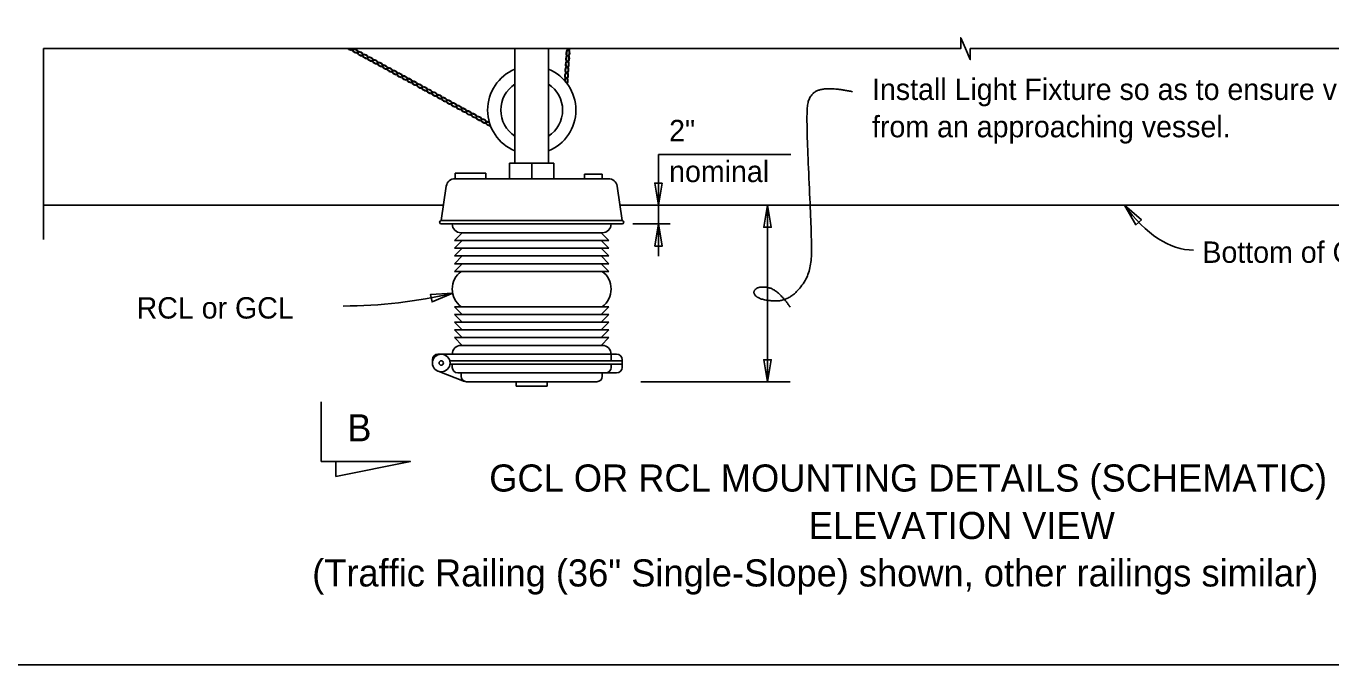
# Model space of a CAD drawing. Extents: x 0 to 20.5, y 0 to 13.
# Drawn here: x 5.78 to 11.94, y 0 to 3.02 of the extents above; entities that cross this region are included whole.
import ezdxf

# ---------------------------------------------------------------- set-up
doc = ezdxf.new("R2010")
doc.units = 0
for name, color, linetype in [('ActivePts-ConstElements', 7, 'Continuous'), ('Dimension', 7, 'Continuous'), ('Miscellaneous', 7, 'Continuous'), ('Miscellaneous1', 7, 'Continuous'), ('NavLight', 7, 'Continuous'), ('SupstrConc', 7, 'Continuous'), ('TextStructures', 7, 'Continuous')]:
    doc.layers.add(name, color=color, linetype=linetype)

msp = doc.modelspace()

# ---------------------------------------------------------------- linework, layer by layer
at = {"layer": 'ActivePts-ConstElements'}
msp.add_lwpolyline([(0, 0), (20.5253, 0), (20.5253, 12.9731), (0, 12.9731)], close=True, dxfattribs=at)
at = {"layer": 'Dimension'}
for p, q in [((8.7613, 2.4096), (8.7613, 2.1697)), ((8.7613, 2.4096), (9.387, 2.4096)), ((8.6296, 2.1697), (8.8874, 2.1697)), ((8.7613, 2.1697), (8.7613, 1.9298)), ((9.2761, 1.3364), (9.2761, 2.1697)), ((8.6404, 2.0813), (8.8171, 2.0813)), ((8.7613, 1.9805), (8.7613, 2.0813)), ((8.6782, 1.3364), (9.3831, 1.3364)), ((7.1685, 1.2409), (7.1685, 0.9597)), ((7.1685, 0.9597), (7.5903, 0.9597)), ((7.5903, 0.9597), (7.2388, 0.8893)), ((7.2388, 0.8893), (7.2388, 0.9597))]:
    msp.add_line(p, q, dxfattribs=at)
for points in [[(5.858, 2.9088), (10.1884, 2.9088), (10.1884, 2.9604), (10.2109, 2.9088), (10.2334, 2.8571), (10.2334, 2.9088), (13.9245, 2.9088)], [(5.858, 2.0075), (5.858, 2.9088)]]:
    msp.add_lwpolyline(points, dxfattribs=at)
for points in [[(8.779, 2.2738), (8.7613, 2.1697), (8.7437, 2.2738)], [(9.2762, 2.1697), (9.2585, 2.0655), (9.2938, 2.0655)], [(10.9625, 2.1697), (11.0148, 2.0779), (11.0421, 2.1003)], [(8.7437, 1.9772), (8.7613, 2.0813), (8.779, 1.9772)], [(7.7898, 1.7541), (7.6843, 1.7477), (7.6923, 1.7134)], [(9.2762, 1.3364), (9.2938, 1.4405), (9.2585, 1.4405)], [(7.2388, 0.9597), (7.2388, 0.8893), (7.5903, 0.9597)]]:
    msp.add_lwpolyline(points, close=True, dxfattribs=at)
msp.add_arc((7.2637, 4.0227), 2.3288, 270.23541, 283.05474, dxfattribs=at)
msp.add_ellipse((11.3056, 3.7942), major_axis=(-0.0171, -1.8368), ratio=0.385201, start_param=5.801208, end_param=6.283151, dxfattribs=at)
msp.add_open_spline([(9.678, 2.7056), (9.5643, 2.7295), (9.4689, 2.6952), (9.4589, 2.5643), (9.4843, 2.0467), (9.4843, 1.8464), (9.3802, 1.7181), (9.2575, 1.7181), (9.2026, 1.752), (9.2317, 1.7891), (9.3253, 1.773), (9.3834, 1.689)], degree=2, dxfattribs=at)
at = {"layer": 'Miscellaneous'}
for p, q in [((7.8347, 2.0396), (7.7983, 2.0031)), ((8.491, 2.0396), (8.5275, 2.0031)), ((7.8347, 2.0031), (7.7983, 1.9667)), ((8.163, 2.003), (7.7984, 2.003)), ((8.1629, 2.003), (8.5276, 2.003)), ((8.491, 2.0031), (8.5275, 1.9667)), ((7.8347, 1.9667), (7.7983, 1.9302)), ((7.8347, 1.9302), (7.7983, 1.8938)), ((8.163, 1.9666), (7.7984, 1.9666)), ((8.163, 1.9301), (7.7984, 1.9301)), ((8.1629, 1.9666), (8.5276, 1.9666)), ((8.1629, 1.9301), (8.5276, 1.9301)), ((8.491, 1.9667), (8.5275, 1.9302)), ((8.491, 1.9302), (8.5275, 1.8938)), ((7.8347, 1.8938), (7.7983, 1.8573)), ((8.163, 1.8937), (7.7984, 1.8937)), ((8.163, 1.8572), (7.7984, 1.8572)), ((8.1629, 1.8937), (8.5276, 1.8937)), ((8.1629, 1.8572), (8.5276, 1.8572)), ((8.491, 1.8938), (8.5275, 1.8573)), ((7.8347, 1.6542), (7.7983, 1.6906)), ((8.163, 1.6905), (7.7984, 1.6905)), ((8.1629, 1.6905), (8.5276, 1.6905)), ((8.491, 1.6542), (8.5275, 1.6906)), ((7.8347, 1.6177), (7.7983, 1.6542)), ((7.8347, 1.5813), (7.7983, 1.6177)), ((8.163, 1.6541), (7.7984, 1.6541)), ((8.163, 1.6176), (7.7984, 1.6176)), ((8.1629, 1.6541), (8.5276, 1.6541)), ((8.1629, 1.6176), (8.5276, 1.6176)), ((8.491, 1.6177), (8.5275, 1.6542)), ((8.491, 1.5813), (8.5275, 1.6177)), ((7.8347, 1.5448), (7.7983, 1.5813)), ((7.8347, 1.5083), (7.7983, 1.5448)), ((8.163, 1.5812), (7.7984, 1.5812)), ((8.163, 1.5447), (7.7984, 1.5447)), ((8.1629, 1.5812), (8.5276, 1.5812)), ((8.1629, 1.5447), (8.5276, 1.5447)), ((8.491, 1.5448), (8.5275, 1.5813)), ((8.491, 1.5083), (8.5275, 1.5448))]:
    msp.add_line(p, q, dxfattribs=at)
for centre, radius, start, end in [((8.1629, 2.6189), 0.2084, 112.30644, 247.69356), ((8.1629, 2.6189), 0.2084, 292.32192, 67.67808), ((8.1629, 2.6189), 0.146, 122.80227, 237.19773), ((8.1629, 2.6189), 0.146, 302.82659, 57.17341), ((7.8919, 1.774), 0.1041, 126.81262, 233.18738), ((8.4338, 1.774), 0.1041, 306.81262, 53.18738)]:
    msp.add_arc(centre, radius, start, end, dxfattribs=at)
for centre, major_axis, ratio, start_param, end_param in [((7.3069, 2.9104), (-0.0135, 0.0073), 0.530594, 0.963145, 3.776778), ((7.3069, 2.9104), (-0.0117, 0.0064), 0.458548, 1.074165, 3.810831), ((8.3359, 2.9152), (0.001, 0.0153), 0.530594, 2.038886, 4.311456), ((8.3359, 2.9152), (0.0008, 0.0133), 0.458548, 2.106923, 4.234305), ((8.3258, 2.7561), (0.001, 0.0153), 0.530594, 3.785956, 7.749185), ((8.3258, 2.7561), (0.0008, 0.0133), 0.458548, 3.769896, 7.882867), ((7.9599, 2.5543), (-0.0135, 0.0073), 0.530594, 4.817186, 8.780415), ((7.9599, 2.5543), (-0.0117, 0.0064), 0.458548, 4.683503, 8.796475)]:
    msp.add_ellipse(centre, major_axis=major_axis, ratio=ratio, start_param=start_param, end_param=end_param, dxfattribs=at)
for centre, major_axis, ratio in [((7.3302, 2.8977), (-0.0135, 0.0073), 0.530594), ((7.3302, 2.8977), (-0.0117, 0.0064), 0.458548), ((7.3535, 2.885), (-0.0135, 0.0073), 0.530594), ((8.3342, 2.8887), (0.001, 0.0153), 0.530594), ((8.3342, 2.8887), (0.0008, 0.0133), 0.458548), ((7.3535, 2.885), (-0.0117, 0.0064), 0.458548), ((7.3769, 2.8723), (-0.0135, 0.0073), 0.530594), ((7.3769, 2.8723), (-0.0117, 0.0064), 0.458548), ((7.4002, 2.8596), (-0.0135, 0.0073), 0.530594), ((7.4002, 2.8596), (-0.0117, 0.0064), 0.458548), ((7.4235, 2.8468), (-0.0135, 0.0073), 0.530594), ((7.4235, 2.8468), (-0.0117, 0.0064), 0.458548), ((7.4468, 2.8341), (-0.0135, 0.0073), 0.530594), ((7.4468, 2.8341), (-0.0117, 0.0064), 0.458548), ((8.3309, 2.8357), (0.001, 0.0153), 0.530594), ((8.3326, 2.8622), (0.001, 0.0153), 0.530594), ((8.3309, 2.8357), (0.0008, 0.0133), 0.458548), ((8.3326, 2.8622), (0.0008, 0.0133), 0.458548), ((7.4701, 2.8214), (-0.0135, 0.0073), 0.530594), ((7.4701, 2.8214), (-0.0117, 0.0064), 0.458548), ((7.4935, 2.8087), (-0.0135, 0.0073), 0.530594), ((7.4935, 2.8087), (-0.0117, 0.0064), 0.458548), ((7.5168, 2.796), (-0.0135, 0.0073), 0.530594), ((7.5168, 2.796), (-0.0117, 0.0064), 0.458548), ((7.5401, 2.7832), (-0.0135, 0.0073), 0.530594), ((7.5401, 2.7832), (-0.0117, 0.0064), 0.458548), ((7.5634, 2.7705), (-0.0135, 0.0073), 0.530594), ((7.5634, 2.7705), (-0.0117, 0.0064), 0.458548), ((8.3275, 2.7826), (0.001, 0.0153), 0.530594), ((8.3292, 2.8092), (0.001, 0.0153), 0.530594), ((8.3275, 2.7826), (0.0008, 0.0133), 0.458548), ((8.3292, 2.8092), (0.0008, 0.0133), 0.458548), ((7.5868, 2.7578), (-0.0135, 0.0073), 0.530594), ((7.5868, 2.7578), (-0.0117, 0.0064), 0.458548), ((7.6101, 2.7451), (-0.0135, 0.0073), 0.530594), ((7.6101, 2.7451), (-0.0117, 0.0064), 0.458548), ((7.6334, 2.7324), (-0.0135, 0.0073), 0.530594), ((7.6334, 2.7324), (-0.0117, 0.0064), 0.458548), ((7.6567, 2.7196), (-0.0135, 0.0073), 0.530594), ((7.6567, 2.7196), (-0.0117, 0.0064), 0.458548), ((7.6801, 2.7069), (-0.0135, 0.0073), 0.530594), ((7.6801, 2.7069), (-0.0117, 0.0064), 0.458548), ((7.7034, 2.6942), (-0.0135, 0.0073), 0.530594), ((7.7034, 2.6942), (-0.0117, 0.0064), 0.458548), ((7.7267, 2.6815), (-0.0135, 0.0073), 0.530594), ((7.7267, 2.6815), (-0.0117, 0.0064), 0.458548), ((7.75, 2.6687), (-0.0135, 0.0073), 0.530594), ((7.75, 2.6687), (-0.0117, 0.0064), 0.458548), ((7.7733, 2.656), (-0.0135, 0.0073), 0.530594), ((7.7733, 2.656), (-0.0117, 0.0064), 0.458548), ((7.7967, 2.6433), (-0.0135, 0.0073), 0.530594), ((7.7967, 2.6433), (-0.0117, 0.0064), 0.458548), ((7.82, 2.6306), (-0.0135, 0.0073), 0.530594), ((7.82, 2.6306), (-0.0117, 0.0064), 0.458548), ((7.8433, 2.6179), (-0.0135, 0.0073), 0.530594), ((7.8433, 2.6179), (-0.0117, 0.0064), 0.458548), ((7.8666, 2.6051), (-0.0135, 0.0073), 0.530594), ((7.8666, 2.6051), (-0.0117, 0.0064), 0.458548), ((7.89, 2.5924), (-0.0135, 0.0073), 0.530594), ((7.89, 2.5924), (-0.0117, 0.0064), 0.458548), ((7.9133, 2.5797), (-0.0135, 0.0073), 0.530594), ((7.9133, 2.5797), (-0.0117, 0.0064), 0.458548), ((7.9366, 2.567), (-0.0135, 0.0073), 0.530594), ((7.9366, 2.567), (-0.0117, 0.0064), 0.458548)]:
    msp.add_ellipse(centre, major_axis=major_axis, ratio=ratio, dxfattribs=at)
at = {"layer": 'Miscellaneous1'}
msp.add_lwpolyline([(0, 12.9731), (20.5253, 12.9731), (20.5253, 0), (0, 0)], close=True, dxfattribs=at)
at = {"layer": 'NavLight'}
for p, q in [((8.0838, 2.9088), (8.0838, 2.3677)), ((8.2421, 2.9088), (8.2421, 2.3677)), ((8.2671, 2.3677), (8.0587, 2.3677)), ((8.0588, 2.3676), (8.0588, 2.2948)), ((8.163, 2.3676), (8.163, 2.2948)), ((8.2672, 2.3676), (8.2672, 2.2948)), ((7.8009, 2.3208), (7.8009, 2.2948)), ((7.9467, 2.3208), (7.8009, 2.3208)), ((8.1629, 2.2948), (7.8009, 2.2948)), ((7.9467, 2.3208), (7.9467, 2.2948)), ((8.1629, 2.2948), (8.5249, 2.2948)), ((8.4129, 2.3156), (8.4962, 2.3156)), ((8.4129, 2.3156), (8.4129, 2.2948)), ((8.4962, 2.3156), (8.4962, 2.2948)), ((7.7356, 2.097), (7.7597, 2.2593)), ((8.59, 2.097), (8.5659, 2.2593)), ((8.1628, 2.0969), (7.7357, 2.0969)), ((8.1628, 2.0969), (8.59, 2.0969)), ((8.1628, 2.0813), (7.7357, 2.0813)), ((8.1628, 2.0396), (7.8296, 2.0396)), ((8.1628, 2.0813), (8.59, 2.0813)), ((8.1629, 2.0396), (8.4962, 2.0396)), ((8.1628, 1.5083), (7.8296, 1.5083)), ((8.1629, 1.5083), (8.4962, 1.5083)), ((7.6941, 1.4406), (7.6941, 1.425)), ((8.1629, 1.4666), (7.7201, 1.4666)), ((8.163, 1.4353), (7.7762, 1.4353)), ((8.163, 1.4197), (7.7771, 1.4197)), ((7.7879, 1.4198), (7.7879, 1.4041)), ((8.1629, 1.4666), (8.564, 1.4666)), ((8.163, 1.4353), (8.5901, 1.4353)), ((8.163, 1.4197), (8.5901, 1.4197)), ((8.5379, 1.4354), (8.5379, 1.4666)), ((8.5379, 1.4198), (8.5379, 1.4041)), ((8.59, 1.4406), (8.59, 1.4041)), ((7.8463, 1.3381), (7.7209, 1.3861)), ((8.1629, 1.3781), (7.8139, 1.3781)), ((7.8296, 1.3781), (7.8296, 1.3624)), ((8.1629, 1.3781), (8.564, 1.3781)), ((8.4962, 1.3781), (8.4962, 1.3624)), ((8.1629, 1.3364), (7.8556, 1.3364)), ((8.0901, 1.3155), (8.0901, 1.3363)), ((8.163, 1.3155), (8.0901, 1.3155)), ((8.1629, 1.3364), (8.4702, 1.3364)), ((8.163, 1.3155), (8.2359, 1.3155)), ((8.2359, 1.3155), (8.2359, 1.3363))]:
    msp.add_line(p, q, dxfattribs=at)
for radius in [0.0416, 0.0104]:
    msp.add_circle((7.7357, 1.425), radius, dxfattribs=at)
for centre, radius, start, end in [((7.8009, 2.2532), 0.0417, 90, 171.57567), ((8.5247, 2.2532), 0.0417, 8.42433, 90), ((7.7357, 2.0891), 0.00781, 90, 270), ((8.59, 2.0891), 0.00781, 270, 90), ((7.8295, 2.0813), 0.0417, 180, 270), ((8.4962, 2.0813), 0.0417, 270, 360), ((7.8295, 1.4666), 0.0417, 90, 180), ((8.4962, 1.4666), 0.0417, 0, 90), ((7.7201, 1.4406), 0.026, 90, 180), ((8.564, 1.4406), 0.026, 0, 90), ((7.8139, 1.4041), 0.026, 180, 270), ((7.8556, 1.3624), 0.026, 180, 270), ((8.4702, 1.3624), 0.026, 270, 0), ((8.5119, 1.4041), 0.026, 270, 0), ((8.564, 1.4041), 0.026, 270.00345, 360)]:
    msp.add_arc(centre, radius, start, end, dxfattribs=at)
at = {"layer": 'SupstrConc'}
for p, q in [((5.858, 2.1697), (7.7464, 2.1697)), ((8.5792, 2.1697), (13.9245, 2.1697))]:
    msp.add_line(p, q, dxfattribs=at)

# ---------------------------------------------------------------- texts
at = {"layer": 'Dimension'}
for s, height, p in [('Install Light Fixture so as to ensure visibility ', 0.1008, (9.7699, 2.6664)), ('from an approaching vessel.', 0.1008, (9.7699, 2.4904)), ('2"', 0.1008, (8.8118, 2.4718)), ('nominal', 0.1008, (8.8118, 2.2788)), ('GCL OR RCL MOUNTING DETAILS (SCHEMATIC)', 0.128, (7.9623, 0.8181)), ('ELEVATION VIEW', 0.128, (9.4708, 0.5941)), ('(Traffic Railing (36" Single-Slope) shown, other railings similar)', 0.128, (7.1263, 0.3701))]:
    msp.add_text(s, height=height, dxfattribs=at).set_placement(p)
at = {"layer": 'TextStructures'}
for s, height, p in [('Bottom of Girder', 0.1008, (11.33, 1.8977)), ('RCL or GCL', 0.1008, (6.2976, 1.6347)), ('B', 0.128, (7.2921, 1.0551))]:
    msp.add_text(s, height=height, dxfattribs=at).set_placement(p)

doc.saveas('drawing.dxf')
